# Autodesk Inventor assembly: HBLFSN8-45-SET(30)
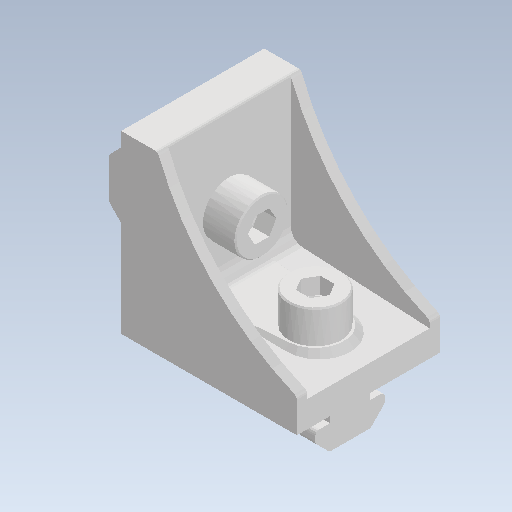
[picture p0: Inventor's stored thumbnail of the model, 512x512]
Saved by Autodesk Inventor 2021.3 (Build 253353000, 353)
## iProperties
Created: 2022-02
Part Number: HBLFSN8-45-SET(30)
Document SubType Name: Assembly
Designer: kengo
Author: kengo
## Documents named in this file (4)
- C:\Users\kengo\Documents\S2S_frame\SDC345\frame_misumi_ver12\HBLFSN8-45-SET(30).iam
- C:\Users\kengo\Documents\S2S_frame\SDC345\frame_misumi_ver12\HBLFSN8-45.ipt
- C:\Users\kengo\Documents\S2S_frame\SDC345\frame_misumi_ver12\HNTT8-8.ipt
- C:\Users\kengo\Documents\S2S_frame\SDC345\frame_misumi_ver12\CBM8-20.ipt
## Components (5 placed, 3 different names)
1. HBLFSN8-45
2. HNTT8-8
3. CBM8-20
4. HNTT8-8:1
5. CBM8-20:1
